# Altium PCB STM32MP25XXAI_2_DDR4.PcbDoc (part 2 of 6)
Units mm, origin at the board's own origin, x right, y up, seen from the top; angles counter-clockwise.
Board outline 172 x 137 mm, 4 copper layers (Top Layer, Signal Layer 1, Signal Layer 2, Bottom Layer), stack 1.614 mm thick; 241 components, 153 nets, 1312 pads, 924 vias.
Unrouted connection lines stored in the file: 13.
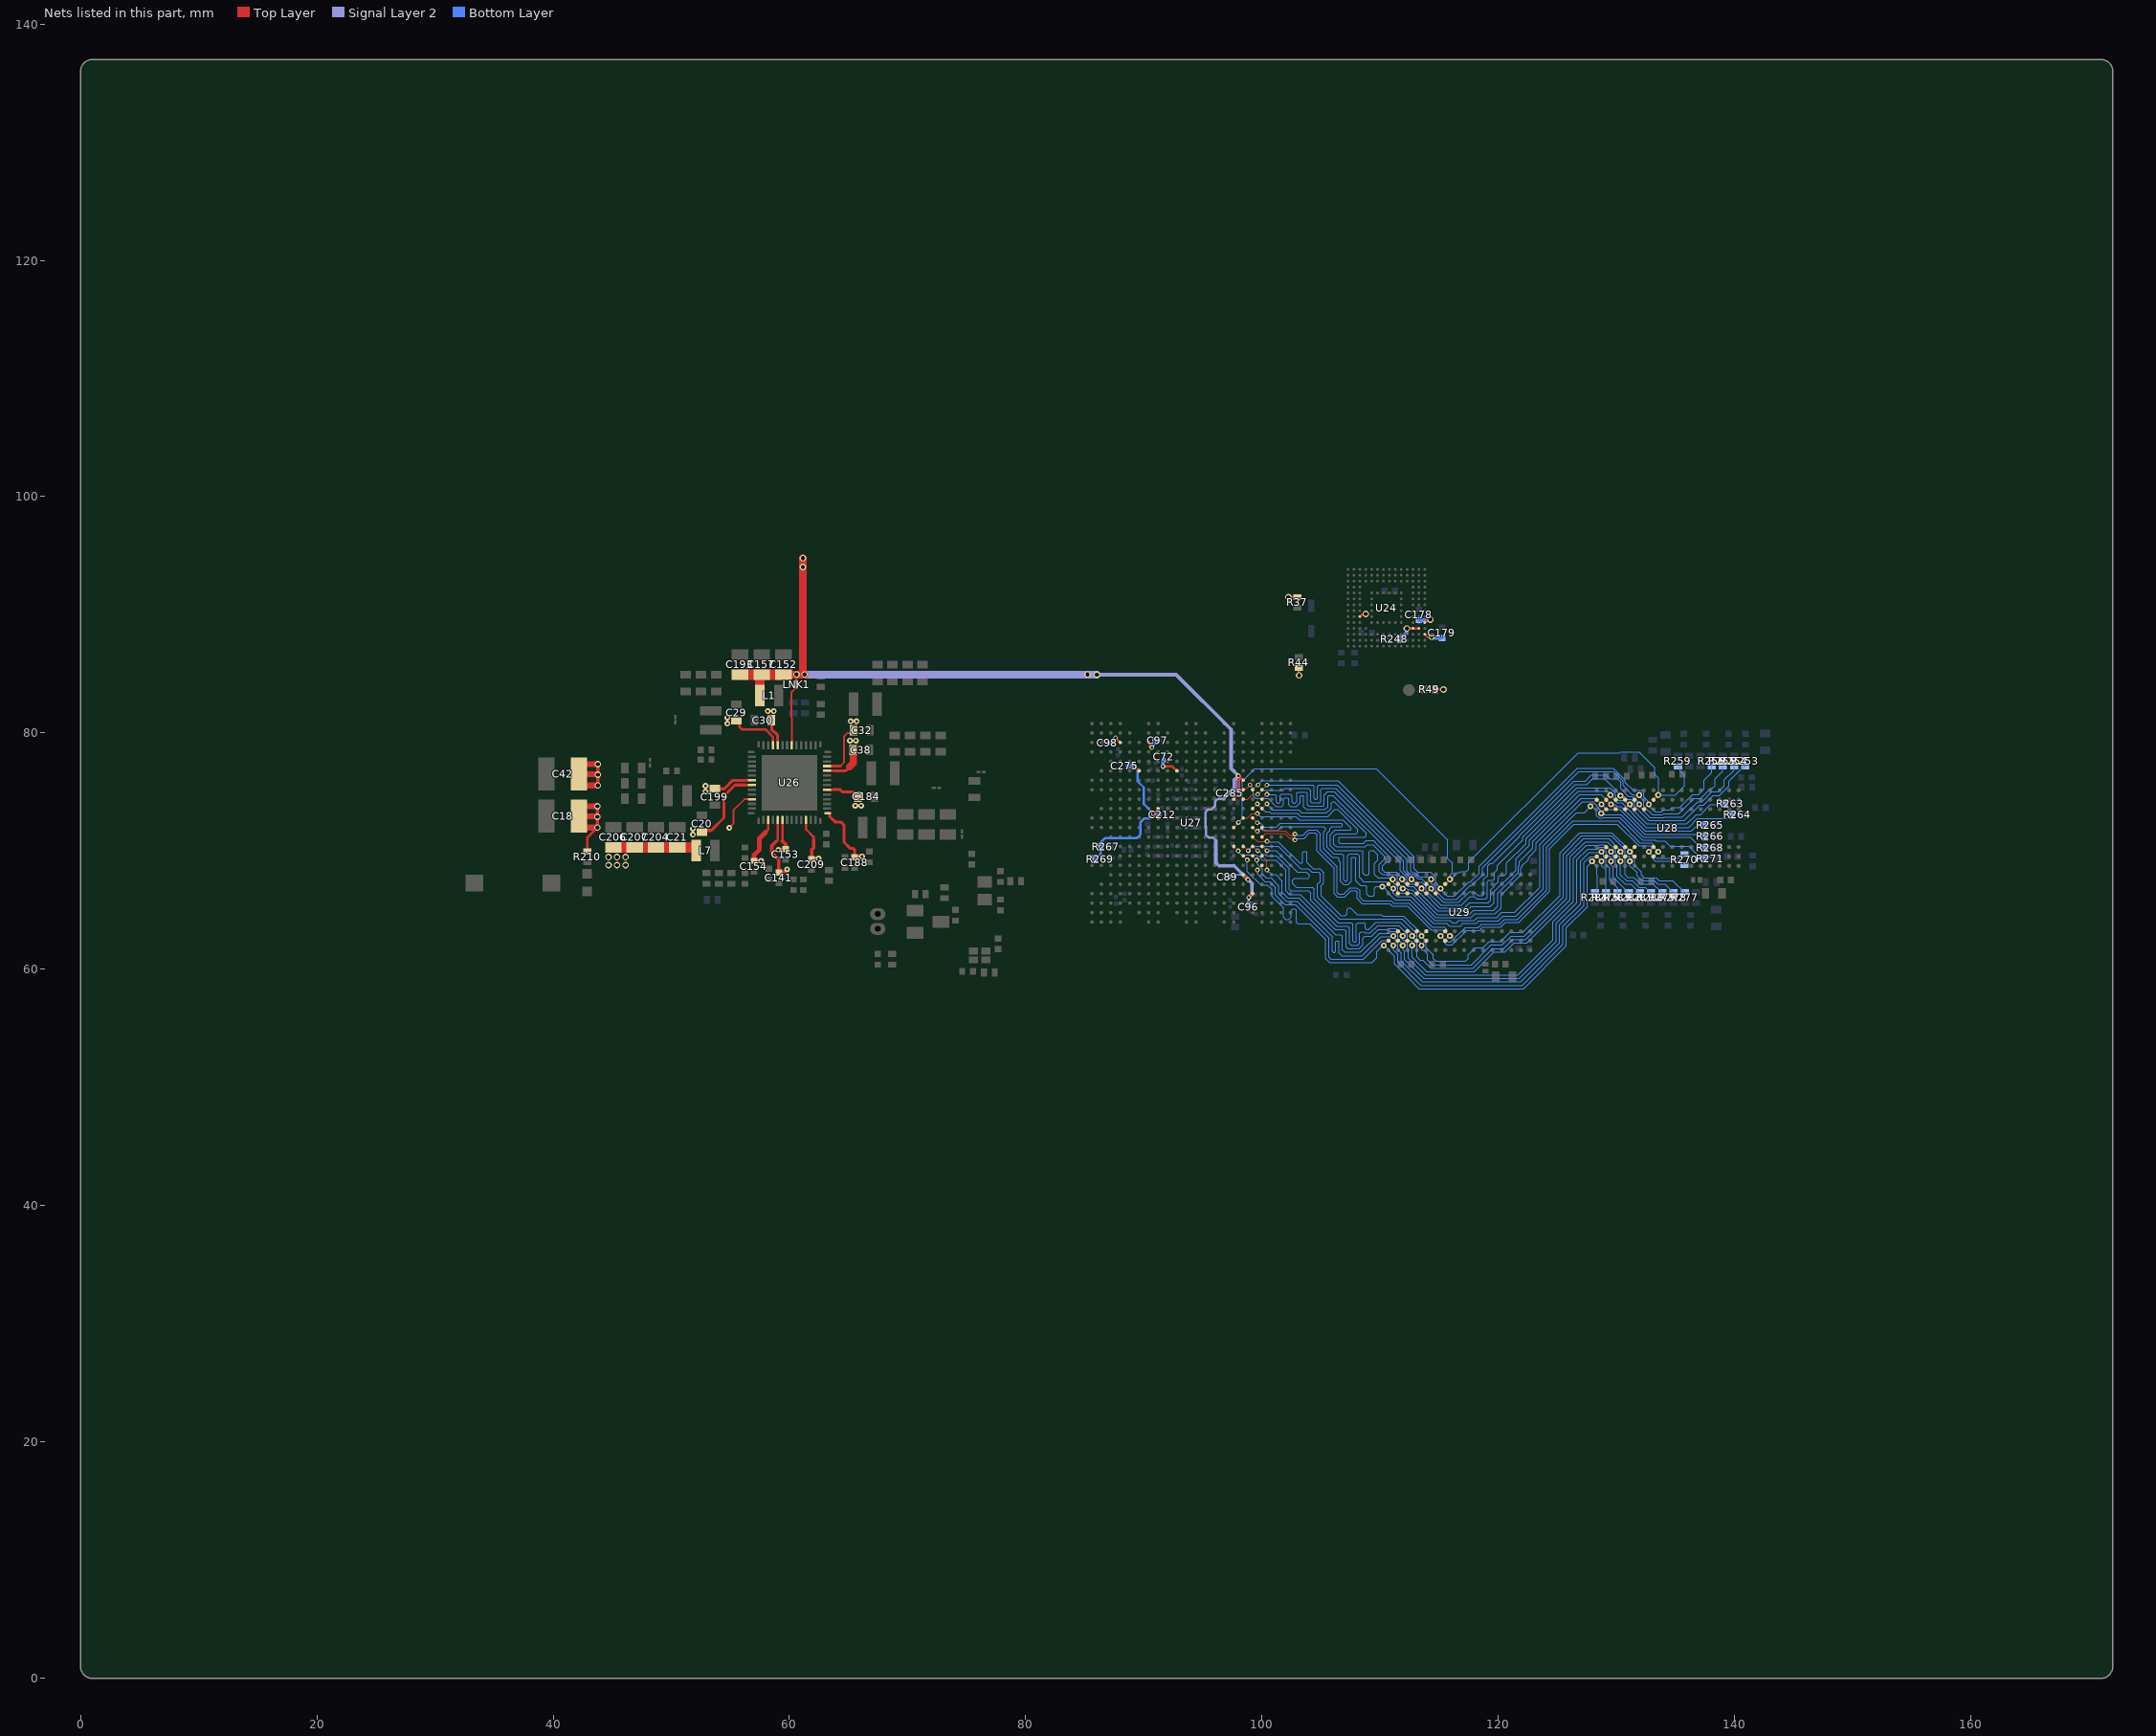
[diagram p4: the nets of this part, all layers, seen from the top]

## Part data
B2: library part MCD-03492, "Switch tactile, SPST-NO, 50mA, 12V, 6x3.8mm", Manufacturer="WURTH ELEKTRONIK", Manufacturer_Part_Number=434121025816, Package=6x3.8mm
C1 C2 C3 C4 C5 C6 C7 C8 C9 C10 C11 C12 C13 C14 C15 C16 C17 C25 C31 C44 C45 C46 C47 C52 C53 C54 C55 C56 C57 C58 C59 C60 C67: library part MCD-02377, "Capacitor, MLCC, 1uF, 6.3V, X5R, +/-20%, 0201, T=0,3mm", Alternate_Manufacturer=N/A, Manufacturer=MURATA, Manufacturer_Part_Number=GRM033R60J105MEA2, Package=0201
C18 C42: library part MCD-01796, "Capacitor, Tantalum, 100uF, 6V3, 40mR, +/-20%,  Type_B (3528 metric), T=1.9mm", Manufacturer=AVX, Manufacturer_Part_Number=TCJB107M006R0040, Package="3528 (metric)"
C19 C21 C152 C157 C186 C187 C193 C204 C206 C207: library part MCD-03139, "Capacitor, MLCC, 22uF, 10V, X5R, +/-20%, 0805, T=1,25mm", Manufacturer=MURATA, Manufacturer_Part_Number=GRM21BR61A226ME51L, Package=0805
C20 C29 C30 C32 C38 C184 C199: library part MCD-00099, "Capacitor, MLCC, 10uF, 10V, X5R, +/-10%, 0603, T=0,8mm", Alternate_Manufacturer=N/A, Manufacturer=MURATA, Manufacturer_Part_Number=GRM188R61A106KE69D, Package=0603
C22 C23 C24 C26 C27 C28 C34 C35 C36 C37 C41 C183 C200 C202: library part MCD-00100, "Capacitor, MLCC, 22uF, 6V3, X5R, +/-20%, 0603, T=0,8mm", Alternate_Manufacturer=N/A, Manufacturer=MURATA, Manufacturer_Part_Number=GRM188R60J226MEA0J, Package=0603
C33: library part MCD-00011, "Capacitor, MLCC, 10nF, 16V, X7R, 10%, 0402, T=0.5mm", Manufacturer=YAGEO, Manufacturer_Part_Number=CC0402KRX7R7BB103, Package=0402
C39 C40: library part MCD-03140, "Capacitor, MLCC, 10uF, 6.3V, X5R, +/-20%, 0402, T=0.5mm", Manufacturer=MURATA, Manufacturer_Part_Number=GRM155R60J106ME05D, Package=0402
C43 C153 C154 C188: library part MCD-00095, "Capacitor, MLCC, 1uF, 25V, X5R, +/-10%, 0402, T=0.5mm", Manufacturer=MURATA, Manufacturer_Part_Number=GRM155R61E105KA12, Package=0402
C48 C49 C50 C51 C76 C77 C78 C80 C82 C83 C84 C93 C94 C95 C177 C179 C182 C211 C226 C238 C239 C245 C247 C255 C256 C257 C258 C259 C261 C262 C264 C276 C277 C279 C280 C282 C283 C284: library part MCD-00006, "Capacitor, MLCC, 100nF, 16V, X7R, +/-10%, 0402, T=0.5mm", Alternate_Manufacturer=MURATA, Alternate_Manufacturer_Part_Number=GCM155R71C104KA55D, Manufacturer=YAGEO, Manufacturer_Part_Number=CC0402KRX7R7BB104, Package=0402
C61: library part MCD-01534, "Capacitor, MLCC, 4,7uF, 6V3, X5R, +/-20%, 0201, T=0.5mm", Alternate_Manufacturer=N/A, Manufacturer=MURATA, Manufacturer_Part_Number=GRM035R60J475ME15, Package=0201
C62 C63 C64 C65 C66 C68 C69 C70 C71 C72 C73 C74 C75 C89 C96 C97 C98 C212 C234 C275 C285: library part MCD-01535, "Capacitor, MLCC,100nF, 10V, X7R, +/-10%, 0201, T=0.3mm", Alternate_Manufacturer=N/A, Manufacturer=MURATA, Manufacturer_Part_Number=GRM033R61A104KE15, Package=0201
C79: library part MCD-02235, "Capacitor, MLCC, 2.2uF, 10V, X5R,+/-10%, 0201, T=0.5mm", Manufacturer=MURATA, Manufacturer_Part_Number=GRM033R61A225KE47D, Package=0201
C81 C86 C90 C92: library part MCD-00674, "Capacitor, MLCC, 6.8pF, 50V, NPO, +-0.25pF, 0402, T=0.5mm", Alternate_Manufacturer=N/A, Manufacturer=YAGEO, Manufacturer_Part_Number=CC0402CRNPO9BN6R8, Package=0402
C85 C99 C236 C278: library part MCD-01341, "Capacitor, MLCC, 10uF, 6V3, X5R, +/-20%, 0603, T=0,8mm", Alternate_Manufacturer=MURATA, Alternate_Manufacturer_Part_Number=GRM188R60J106ME84D, Manufacturer_Part_Number=GRM188R60J106ME47D, Package=0603
C87: library part MCD-00006, "Capacitor,100nF,16V,X7R,10%,0402", Alternate_Manufacturer=MURATA, Alternate_Manufacturer_Part_Number=GCM155R71C104KA55D, Manufacturer=YAGEO, Manufacturer_Part_Number=CC0402KRX7R7BB104, Package=0402
C88: library part MCD-01823, "Capacitor, MLCC, 2.2uF, 6V3, X5R,+/-10%, 0402, T=0.5mm", Alternate_Manufacturer=N/A, Manufacturer=MURATA, Manufacturer_Part_Number=GRM155R60J225KE95D, Package=0402
C91 C141 C142 C156 C189 C190 C208 C209 C217: library part MCD-01356, "Capacitor, MLCC, 4.7uF, 6V3, X5R, +/-20%, 0402, T=0.5mm", Manufacturer=MURATA, Manufacturer_Part_Number=GRM155R60J475ME47, Package=0402
C155: library part MCD-02198, "Capacitor, MLCC, 10nF, 50V, X7R, +/-10%, 0402, T=0.5mm", Manufacturer=YAGEO, Manufacturer_Part_Number=CC0402KRX7R9BB103, Package=0402
C178 C180 C181: library part MCD-02606, "Capacitor, MLCC, 2.2uF, 6.3V, X5R, +/-10%, 0402, T=0.5mm", Manufacturer=YAGEO, Manufacturer_Part_Number=CC0402KRX5R5BB225, Package=0402
C254 C281: library part MCD-00099, "Capacitor, MLCC, 10uF, 10V, X5R, +/-10%, 0603, T=0.8mm", Manufacturer=MURATA, Manufacturer_Part_Number=GRM188R61A106KE69D, Package=0603
CN12: library part MCD-00655, "Header 2 circuits, 1.25mm Pitch ,  Vertical, with Friction Lock", Alternate_Manufacturer=N/A, Manufacturer=MOLEX, Manufacturer_Part_Number=53047-0210
D5: library part MCD-00034, Manufacturer=STMICROELECTRONICS, Manufacturer_HQ_COO=EU, Package=SOD323
D6: library part MCD-03280, "Diode, Schottky, Dual Common Cathode, 0V3, 300mA, 40V, SOT-23", Manufacturer=STMICROELECTRONICS, Manufacturer_Part_Number=BAT54CFILM, Package=SOT23
L1 L6: library part MCD-03143, "Inductor, 2.2uH, +/-20%, Itemp= 1700mA, Isat= 2400mA, 0R140, 0806, T=1mm", Manufacturer=MURATA, Manufacturer_Part_Number=DFE201610E-2R2M{}P2, Package=0806
L2 L4: library part MCD-03142, "Inductor, 0.68uH, +/-20%, Itemp= 3900mA, Isat= 5400mA, 0R031, 1008, T=1.2mm", Manufacturer=MURATA, Manufacturer_Part_Number=DFE252012F-R68M{}P2, Package=1008
L3 L5 L7: library part MCD-03141, "Inductor, 0.68uH, +/-20%, Itemp= 3100mA, Isat= 4300mA, 0R043, 0806, T=1mm", Manufacturer=MURATA, Manufacturer_Part_Number=DFE201610E-R68M{}P2, Package=0806
LD11: library part MCD-00588, "LED Green, 0603 SMD, Forward Voltage Typ=2V, Max=2.5V", Alternate_Manufacturer="VISHAY SEMICONDUCTOR OPTO DIVISION", Alternate_Manufacturer_Part_Number=VLMTG1300-GS08, Manufacturer="OSRAM OPTO SEMICONDUCTORS", Manufacturer_Part_Number="LG Q396-PS-35", Package=0603
LNK1 LNK2 LNK4 LNK7 LNK8 LNK11: library part MCD-02777, "Track link on PCB 200um width for layout routing", Manufacturer=N/A
R2 R46 R57 R59 R60 R64 R75 R81 R267 R269 R286: library part MCD-00052, "Resistor,0R,0402,5%,1/16W", Alternate_Manufacturer=N/A, Manufacturer=YAGEO, Manufacturer_Part_Number=RC0402JR-070RL, Package=0402
R27 R252 R272: library part MCD-00053, "Resistor,10K,0402,1%,1/16W", Alternate_Manufacturer=N/A, Manufacturer=YAGEO, Manufacturer_Part_Number=RC0402FR-0710KL, Package=0402
R37 R44 R49 R248: library part MCD-00053, "Resistor,10K,0402,1%,1/16W", Manufacturer=YAGEO, Manufacturer_Part_Number=RC0402FR-0710KL, Package=0402
R63 R73 R262: library part MCD-02253, "Resistor,240R,0201,1%,1/20W", Alternate_Manufacturer=N/A, Manufacturer=YAGEO, Manufacturer_Part_Number=RC0201FR-07240RL, Package=0201
R66: library part MCD-00058, "Resistor, 20R, 0402, +/-1%, 1/16W", Alternate_Manufacturer=N/A, Manufacturer=YAGEO, Manufacturer_Part_Number=RC0402FR-0720RL, Package=0402
R67: library part MCD-00052, "Resistor, 0R, 0402, +/-5%, 1/16W", Manufacturer=YAGEO, Manufacturer_Part_Number=RC0402JR-070RL, Package=0402
R210: library part MCD-00441, "Resistor,270R,0402,1%,1/16W", Manufacturer=YAGEO, Manufacturer_Part_Number=RC0402FR-07270RL, Package=0402
R249: library part MCD-00056, "Resistor, 0R, 0603, +/-5%, 1/10W", Manufacturer=YAGEO, Manufacturer_Part_Number=RC0603JR-070RL, Package=0603
R253 R254 R255 R256 R257 R258 R259 R263 R264 R265 R266 R268 R271 R273 R275 R276 R277 R278 R279 R280 R281 R282 R283 R284: library part MCD-00054, "Resistor, 56R, 0402, +/-1%, 1/16W", Alternate_Manufacturer=N/A, Manufacturer=YAGEO, Manufacturer_Part_Number=RC0402FR-0756RL, Package=0402
R260 R261: library part MCD-00068, "Resistor,1K5,0402,1%,1/16W", Manufacturer=YAGEO, Manufacturer_Part_Number=RC0402FR-071K5L, Package=0402
R270: library part MCD-01819, "Resistor,100R,0402,0,5%,1/16W,±100ppm/°C", Alternate_Manufacturer=N/A, Manufacturer=YAGEO, Manufacturer_Part_Number=RC0402DR-07100RL, Package=0402
R300 R301 R302 R303: library part MCD-00061, "Resistor, 1K, 0402, +/-1%,1/16W", Manufacturer=YAGEO, Manufacturer_Part_Number=RC0402FR-071KL, Package=0402
TP9: library part MCD-00074, "Test Point 1mm", Manufacturer=n/a, Manufacturer_HQ_COO=Unknown
U24: library part MCD-02799, "Memory, eMMC, 4GB, 15nm ,WFBGA , 153 pins", Manufacturer=KIOXIA, Manufacturer_Part_Number=THGBMTG5D1LBAIL, Package=WFBGA153
U26: library part MCD-03000, "STPMIC2", Manufacturer=STMICROELECTRONICS, Package=VQFN
U27: library part MCD-02000, "MPU, ARM Cortex-A35 + M33 32-bit MPU, 808KB RAM, With Crypto", Manufacturer=STMICROELECTRONICS, Manufacturer_HQ_COO=EU, Package=LFBGA-436
U28: library part MCD-03523, "Memory, DDR4 SDRAM, 1V2, 16Gbit, FBGA96", Manufacturer=MICRON, Package=FBGA-96
U29: library part MCD-03523, "Memory, DDR4 SDRAM, 1V2, 16Gbit, 1.6 GHz, FBGA96", Manufacturer=MICRON, Package=FBGA-96
X1: library part MCD-01479, "Crystal, 32.768kHz, 6pF, +/-20ppm, 80K, 2.05x1.2mm", Manufacturer=NDK, Manufacturer_Part_Number=NX2012SA-32.768KHZ-EXS00A-MU00527, Package=2.05x1.2mm
X2: library part MCD-02344, "Crystal, 40MHz, 6pF, +/-20ppm, 80R, 1.6x1.2mm", Manufacturer=NDK, Manufacturer_Part_Number=NX1612SA-40MHZ-EXS00A-CS13836, Package=1.6x1.2mm

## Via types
v1: diameter 0.55, hole 0.35, Top Layer to Bottom Layer, 432 vias
v2: diameter 0.4, hole 0.2, Top Layer to Bottom Layer, tented both sides, 202 vias
v3: diameter 0.5, hole 0.2, Top Layer to Bottom Layer, 146 vias
v4: diameter 0.5, hole 0.25, Top Layer to Bottom Layer, 144 vias

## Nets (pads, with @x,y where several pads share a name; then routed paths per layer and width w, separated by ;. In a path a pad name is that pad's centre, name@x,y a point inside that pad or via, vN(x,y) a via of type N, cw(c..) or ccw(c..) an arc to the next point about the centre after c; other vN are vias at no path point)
1V8: C72.2 C89.2 C96.2 C97.2 C98.2 C152.2 C157.2 C178.2 C179.2 C193.2 C212.2 C275.2 C285.2 L1.2 LNK1.2 R37.2 R44.2 R49.2 R248.2 R267.2 R269.1 U24.C6 U24.M4 U24.N4 U24.P3 U24.P5 U27.C4 U27.C7 U27.F6 U27.F10 U27.G17 U27.J16 U27.K8 U27.L8 U27.U17 U27.W18 | length 110.6
  Top Layer w0.2: LNK1.2@60.6,84.348 v1(60.6,84.95) ; v2(87.6,79.6) U27.C4@88,79.2 v2(87.6,79.6) ; v2(89.2,77.2) U27.F6@89.6,76.8 ; U27.C7@90.4,79.2 90.415,79.185 90.415,79.02 v2(90.66,78.775) ; U27.L8@91.2,72.8 91.175,72.8 v2(90.8,73.175) 91.2,73.575 U27.K8@91.2,73.6 ; v2(91.624,77.173) 92.413,77.173 92.786,76.8 U27.F10@92.8,76.8 ; U27.J16@97.6,74.4 98,74.8 v2(98,76.375) 98.012,76.375 98.388,76 U27.G17@98.4,76 ; U27.U17@98.4,68 v2(98.8,67.6) ; v2(98.868,66.067) U27.W18@99.2,66.4 ; v1(102.23,91.5) R37.2@102.975,91.5 ; R44.2@103.1,85.528 103.125,85.503 v1(103.125,84.875) ; U24.C6@108.275,89.85 108.452,90.027 108.727,90.027 v1(108.775,90.075) ; v1(112.25,88.85) U24.M4@112.775,88.85 U24.N4@113.275,88.85 ; U24.P3@113.775,88.35 113.975,88.15 v1(114.35,88.15) ; U24.P5@113.775,89.35 114.005,89.58 114.23,89.58 v1(114.25,89.6) ; R49.2@114.625,83.685 v1(115.35,83.685)
  Top Layer w0.64: C152.2@59.5,84.95 v1(60.6,84.95) v1(61.28,84.95) 61.142,85.088 v1(61.142,94.8)
  Top Layer w0.8: L1.2@57.495,83.175 57.495,84.9 57.545,84.95 C157.2@57.65,84.95
  Top Layer w0.9: C193.2@55.8,84.95 C157.2@57.545,84.95 ; C157.2@57.65,84.95 C152.2@59.5,84.95
  Signal Layer 2 w0.2: 96.075,70.9 95.825,71.15 95.484,71.15 95.399,71.235 95.248,71.386 95.248,72.063 95.201,72.109 95.201,73.292 95.317,73.408 95.317,73.433 95.434,73.55 95.723,73.55 96.007,73.834 96.007,74.166 96.003,74.169 96.257,74.423 96.684,74.423 ; v2(98.868,66.067) v2@98.868,66.094
  Signal Layer 2 w0.3: v1(86.019,84.939) 92.721,84.939 97.371,80.289 97.371,77.004 v2(98,76.375) ; 96.075,70.9 96.075,69.048 96.075,69.014 96.339,68.75 97.65,68.75 v2(98.8,67.6) ; 96.684,74.423 97.65,75.389 97.65,76.018 v2@98,76.367 ; v2(98.8,67.6) 99.15,67.25 99.15,66.377 v2@98.868,66.094
  Signal Layer 2 w0.64: v1@60.6,84.955 v1@61.28,84.955 ; v1(61.28,84.95) 86.009,84.95 v1(86.019,84.939)
  Bottom Layer w0.17: C89.2@97.35,67.825 97.415,67.89 97.44,67.89 97.56,68.01 98.39,68.01 v2(98.8,67.6)
  Bottom Layer w0.2: R269.1@85.854,69.315 85.854,69.41 86.009,69.565 86.104,69.565 86.35,69.811 R267.2@86.35,70.375 ; R267.2@86.325,70.715 86.697,71.087 89.377,71.087 89.723,71.434 89.723,72.448 90.059,72.783 90.457,72.783 90.8,73.127 v2(90.8,73.175) ; v2(89.2,77.2) 89.458,76.942 89.458,75.927 89.985,75.4 89.985,73.99 v2(90.8,73.175) ; v2(90.66,78.775) 90.66,78.79 90.825,78.955 C97.2@90.825,79.375 ; C212.2@91.31,73.1 91.272,73.138 90.837,73.138 v2(90.8,73.175) ; C96.2@98.85,65.55 98.85,66.05 v2(98.868,66.067)
  Bottom Layer w0.3: C98.2@87.175,79.175 v2(87.6,79.6) ; C72.2@91.6,77.7 91.6,77.224 91.624,77.2 v2(91.624,77.173) ; C285.2@97.555,74.91 97.94,75.295 97.94,76.288 98,76.348 v2(98,76.375) ; R248.2@111.675,87.95 112.241,88.516 112.241,88.841 v1(112.25,88.85) ; C178.2@113.275,89.55 114.132,89.55 114.182,89.6 v1(114.25,89.6) ; v1(114.35,88.15) 114.418,88.15 114.543,88.025 C179.2@115.225,88.025
  Bottom Layer w0.4: C275.2@88.675,77.2 v2(89.2,77.2)
  other v1: 85.224,84.95 61.131,94.047
1V8_FB: LNK1.1 U26.35 | length 5.1
  Top Layer w0.15: U26.35@60.2,78.97 60.2,81.311 60.175,81.336 60.175,83.473 LNK1.1@60.6,83.898
3V3: C21.2 C154.2 C204.2 C206.2 C207.2 L7.2 U26.3 U26.53 | length 15.3
  Top Layer w0.15: v3(54.91,71.977) 55.262,72.329 55.262,73.465 56.197,74.4 U26.53@56.83,74.4 ; U26.53@56.62,74.369 56.919,74.369 U26.53@56.95,74.4
  Top Layer w0.21: 57.973,71.598 58.2,71.825 U26.3@58.2,72.63
  Top Layer w0.3: C154.2@56.975,69.175 C154.2@57,69.175 v3@57.585,69.175
  Top Layer w0.4: C154.2@57,69.175 57.014,69.189 57.014,69.685 57.46,70.131 57.46,71.085 57.973,71.598
  Top Layer w0.9: C206.2@45.087,70.323 C21.2@50.5,70.323 51.862,70.323 L7.2@51.887,70.298
  other v1: 44.687,68.823 45.412,68.823 46.137,68.823 44.687,69.498 45.412,69.498 46.137,69.498
  other v3: 57.61,69.175
5V_STLK: C18.1 C20.2 C29.2 C30.2 C32.2 C38.2 C42.1 C153.2 C184.2 C188.2 C199.2 C209.2 R210.1 U26.6 U26.11 U26.15 U26.20 U26.24 U26.25 U26.38 U26.39 U26.49 U26.50 | length 56.5
  Top Layer w0.15: 64.3,77.2 64.625,77.525 64.625,79.731 64.888,79.994 65.319,79.994 C32.2@65.425,80.1
  Top Layer w0.2: R210.1@42.887,69.97 42.887,71.138 v1(43.751,72.002)
  Top Layer w0.21: C29.2@55.525,81.05 55.762,80.813 55.762,80.513 55.975,80.3 57.964,80.3 58.6,79.664 U26.39@58.6,78.97 ; 56.275,75.6 U26.50@56.83,75.6 ; 56.275,76 U26.49@56.83,76 ; U26.38@59,78.97 59,79.525 ; 59.4,70.85 U26.6@59.4,72.63 ; U26.11@61.4,72.63 61.4,71.843 62.04,71.203 62.04,70.975 ; U26.15@63.17,73.2 U26.15@63.245,73.2 U26.15@63.285,73.2 ; U26.20@63.17,75.2 63.725,75.2 ; U26.24@63.17,76.8 63.725,76.8 ; U26.25@63.17,77.2 64.3,77.2
  Top Layer w0.25: C20.2@52.6,71.75 53.375,71.75 54.45,72.825 54.45,74.669 55.381,75.6 56.275,75.6 ; C199.2@53.675,75.275 54.491,75.275 55.216,76 56.275,76 ; C30.2@58.425,81.075 58.494,81.006 58.494,80.308 59,79.802 59,79.525 ; 63.395,73.095 63.395,72.947 63.871,72.472 64.353,72.472 64.625,72.2 64.625,70.759 65.134,70.25 65.379,70.25 65.525,70.104 C188.2@65.525,69.55 ; 63.725,75.2 64.288,75.2 64.463,75.025 65.347,75.025 65.472,74.9 65.55,74.9 65.747,74.703 C184.2@65.747,74.625 ; 63.725,76.8 64.75,76.8 65.075,77.125
  Top Layer w0.3: v1(43.751,72.002) v1(43.751,72.902) v1(43.751,73.802) ; v1(43.776,75.565) v1(43.776,76.465) v1(43.776,77.365) ; v3(59.065,70.11) 59.675,70.11 59.674,70.111 59.674,70.576 59.4,70.85 ; C209.2@61.85,69.38 C209.2@61.875,69.38 ; 62.04,70.975 62.04,70.269 61.875,70.104 C209.2@61.875,69.38 ; v3(62.46,69.38) C209.2@61.875,69.38 ; C188.2@65.525,69.55 v3(66.135,69.55)
  Top Layer w0.5: C18.1@42.187,72.049 42.235,72.002 v1(43.751,72.002) ; C18.1@42.187,72.961 43.679,72.961 43.737,72.902 v1(43.751,72.902) ; C42.1@42.187,75.612 42.235,75.565 v1(43.776,75.565) ; C42.1@42.187,76.523 43.704,76.523 43.762,76.465 v1(43.776,76.465) ; C18.1@42.246,73.802 v1(43.751,73.802) ; C42.1@42.246,77.365 v1(43.776,77.365)
  Top Layer w0.6: 65.075,77.125 65.4,77.45 C38.2@65.4,78.175
  other v3: 51.825,71.4 51.825,71.9 65.575,73.85 66.075,73.85 52.9,75.025 52.9,75.525 65.125,79.35 65.625,79.35 54.75,80.8 65.175,81 65.675,81 54.75,81.3 58.175,81.85 58.675,81.85
5V_VCONN: C141.1 U26.5 | length 5.7
  Top Layer w0.21: 58.877,70.828 59,70.95 U26.5@59,72.63
  Top Layer w0.3: 58.877,70.828 58.51,70.46 58.51,69.865 59.1,69.275 C141.1@59.1,68.2 59.539,68.2 v3(59.8,68.46)
DDR_A0: R265.1 U27.K18 U28.P3 U29.P3 | length 57.5
  Top Layer w0.09: U27.K18@99.2,73.6 v2(99.6,74) ; v4(111.9,66.825) 111.941,66.825 112.294,66.472 U29.P3@112.294,66.422 ; v4@129.532,73.928 129.572,73.928 129.925,73.575 U28.P3@129.925,73.55 U28.P3@129.925,73.525
  Bottom Layer w0.09: v2(99.6,74) 100.267,73.333 100.646,73.333 100.771,73.209 102.988,73.209 103.252,72.945 105.581,72.945 106.158,73.522 106.2,73.522 106.384,73.522 108.091,71.815 108.091,71.615 107.965,71.49 106.3,71.49 106.077,71.267 106.077,70.58 106.3,70.357 108.748,70.357 ; 108.748,70.359 108.914,70.526 109.38,70.526 110.359,69.547 110.359,69.324 109.909,68.874 109.909,68.291 110.177,68.022 111.269,68.022 111.449,67.842 111.449,67.352 111.894,66.908 v4@111.938,66.863 ; v4(111.9,66.825) 111.938,66.862 112.233,66.862 112.365,66.73 112.708,66.73 114.805,64.633 117.533,64.633 117.9,65 119.589,65 119.939,65.349 119.939,66.445 121.7,68.206 121.7,68.718 121.76,68.779 121.76,69.109 122.92,70.269 122.92,70.811 126.885,74.775 128.71,74.775 129.525,73.959 v4(129.525,73.95) ; v4@129.551,73.95 129.885,73.95 130.04,73.795 130.363,73.795 132.433,71.725 136.35,71.725 136.825,72.2 R265.1@137.5,72.2
DDR_A1: R281.1 U27.P16 U28.P7 U29.P7 | length 54.7
  Top Layer w0.09: U27.P16@97.6,70.4 v2(97.975,70.025) ; v4(111.9,62.825) U29.P7@112.3,63.225 ; v4@129.54,69.936 U28.P7@129.932,70.328
  Bottom Layer w0.09: v2(97.975,70.025) 97.975,69.95 98.25,69.675 99.45,69.675 99.53,69.595 99.693,69.595 100.029,69.259 101.146,69.259 101.995,68.41 101.995,66.636 102.285,66.347 103.212,66.347 106.181,63.378 106.972,63.378 107.099,63.25 107.099,61.878 107.235,61.742 108.219,61.742 108.555,62.078 108.555,62.657 108.702,62.804 109.281,62.804 109.834,63.357 110.575,63.357 110.675,63.457 111.319,63.457 111.37,63.405 111.9,62.875 v4(111.9,62.825) ; v4@111.9,62.816 111.9,62.504 111.985,62.42 112.064,62.42 112.295,62.189 112.295,61.694 112.365,61.624 112.365,60.958 113.803,59.52 121.655,59.52 124.605,62.47 124.605,64 126.361,65.756 126.361,69.387 127.456,70.482 128.43,70.482 128.483,70.535 129.004,70.535 129.525,70.014 v4(129.525,69.95) 129.525,69.9 129.725,69.7 129.725,69.509 129.92,69.314 129.92,68.88 130.035,68.765 130.035,67.886 130.722,67.2 131.225,67.2 131.9,66.525 R281.1@131.975,66.525
DDR_A2: R268.1 U27.L18 U28.R3 U29.R3 | length 60.6
  Top Layer w0.09: U27.L18@99.2,72.8 v2(99.6,72.4) ; v4(111.1,66.825) 111.141,66.825 111.494,66.472 U29.R3@111.494,66.422 ; v4(128.703,73.185) 128.781,73.263 128.781,73.381 128.908,73.508 129.084,73.508 U28.R3@129.125,73.55
  Bottom Layer w0.09: v2(99.6,72.4) 99.622,72.378 99.872,72.378 100.195,72.055 101.218,72.055 101.528,72.365 106.721,72.365 106.794,72.291 106.794,72.149 106.716,72.07 105.894,72.07 105.758,71.934 105.758,71.768 105.497,71.508 105.497,70.339 106.06,69.777 106.75,69.777 106.925,69.602 106.925,67.578 107.028,67.475 107.168,67.475 107.254,67.56 107.254,69.636 107.395,69.777 108.048,69.777 108.235,69.59 108.235,67.779 108.578,67.437 110.489,67.437 v4(111.1,66.825) 111.103,66.823 111.103,66.466 111.409,66.16 112.571,66.16 114.598,64.133 115.925,64.133 ; 115.925,64.132 116.116,63.94 116.457,63.94 116.65,64.133 117.958,64.133 118.21,64.385 ; 118.212,64.385 118.227,64.401 119.865,64.401 120.277,64.813 121.373,64.813 123.5,66.94 123.5,70.57 127.125,74.195 127.964,74.195 128.055,74.104 128.277,73.882 128.277,73.84 128.635,73.482 128.635,73.253 v4(128.703,73.185) 128.778,73.109 130.37,73.109 132.282,71.197 ; 132.28,71.195 136.23,71.195 137.125,70.3 R268.1@137.5,70.3
DDR_A3: R279.1 U27.P19 U28.N7 U29.N7 | length 57
  Top Layer w0.09: U27.P19@100,70.4 100.038,70.4 100.388,70.05 v2(100.425,70.05) ; v4(112.7,62.825) 112.724,62.825 113.094,63.195 U29.N7@113.094,63.222 ; v4@130.355,69.928 130.725,70.298 U28.N7@130.725,70.325
  Bottom Layer w0.09: v2(100.425,70.05) 101.175,70.05 102.992,68.234 103.762,68.234 103.993,68.003 103.993,67.765 103.94,67.713 102.738,67.713 102.575,67.55 102.575,67.25 102.898,66.927 104.298,66.927 104.415,66.81 104.415,65.963 106.421,63.958 107.549,63.958 107.679,63.828 107.679,62.403 107.759,62.322 107.922,62.322 107.975,62.375 107.975,63.81 108.123,63.958 108.606,63.958 108.725,63.839 108.725,63.481 108.822,63.384 109.037,63.384 109.631,63.978 111.711,63.978 112.661,63.028 112.661,62.864 v4(112.7,62.825) 112.7,62.775 112.9,62.575 112.9,62.384 113.104,62.18 113.104,61.046 113.37,60.78 113.595,60.78 114.275,60.1 117.854,60.1 119.521,61.767 120.455,61.767 121.221,62.533 122.318,62.533 125.781,65.997 125.781,69.627 127.204,71.05 129.338,71.05 130.17,70.217 130.17,70.208 130.325,70.053 130.325,69.9 130.513,69.713 130.513,69.588 130.6,69.5 130.6,69.434 130.72,69.314 130.72,68.021 130.939,67.803 131.443,67.803 132.021,67.225 133.086,67.225 133.376,66.935 133.389,66.935 133.39,66.934 133.417,66.934 133.825,66.525 R279.1@133.875,66.525
  other v4: 130.325,69.95
DDR_A4: R263.1 U27.H17 U28.N3 U29.N3 | length 59.9
  Top Layer w0.09: U27.H17@98.4,75.2 98.419,75.219 98.604,75.219 v2@98.98,75.595 ; U29.N3@113.094,66.422 113.094,66.47 113.449,66.825 v4@113.5,66.825 ; U28.N3@130.725,73.525 130.725,73.573 131.102,73.95 v4(131.125,73.95)
  Bottom Layer w0.09: v2(98.98,75.6) 99.255,75.325 99.255,74.682 99.484,74.453 100.517,74.453 101.181,73.789 101.696,73.789 101.829,73.922 101.829,74.427 101.924,74.522 102.164,74.522 102.256,74.429 102.256,73.922 102.389,73.789 102.904,73.789 103.221,74.105 103.221,74.641 103.3,74.72 103.458,74.72 103.528,74.65 103.528,73.747 103.751,73.525 105.341,73.525 105.563,73.747 105.563,74.638 105.65,74.725 106.001,74.725 111.695,69.031 111.695,68.342 112.251,67.787 112.251,67.397 112.438,67.21 112.85,67.21 113.002,67.059 113.267,67.059 113.5,66.825 113.5,66.718 113.498,66.715 115.031,65.182 117.108,65.182 117.55,65.625 119.139,65.625 119.359,65.844 119.359,66.748 120.012,67.402 120.012,67.833 120.125,67.945 120.508,67.945 120.695,68.133 120.695,68.98 122.34,70.625 122.34,71.051 126.645,75.355 129.429,75.355 129.87,74.914 129.87,74.756 129.925,74.701 129.925,74.541 130.161,74.305 130.651,74.305 131.006,73.95 v4(131.125,73.95) 131.125,73.825 131.395,73.555 131.395,73.47 132.56,72.305 135.952,72.305 136.748,73.101 137.126,73.101 137.95,73.925 R263.1@139.2,73.925
  other v4: 113.5,66.85
DDR_A5: R282.1 U27.R19 U28.P8 U29.P8 | length 50.8
  Top Layer w0.09: U27.R19@100,69.6 100.4,69.2 v2(100.4,68.4) ; v4(111.9,62.025) 111.9,62.055 U29.P8@112.269,62.424 ; v4@129.532,69.158 U28.P8@129.901,69.527
  Bottom Layer w0.09: v2(100.4,68.4) 100.785,68.015 101.15,68.015 101.705,67.46 101.705,66.516 102.165,66.057 103.092,66.057 106.228,62.92 106.686,62.92 106.809,62.797 106.809,61.639 106.996,61.452 108.339,61.452 109.954,63.067 110.784,63.067 110.937,63.22 111.264,63.22 111.495,62.989 111.495,62.545 111.9,62.14 v4(111.9,62.025) 111.939,61.986 111.939,61.64 112.075,61.504 112.075,60.838 113.683,59.23 121.775,59.23 124.895,62.35 124.895,63.88 126.651,65.636 126.651,69.267 127.574,70.189 128.406,70.189 128.562,70.345 128.889,70.345 129.12,70.114 129.12,69.8 129.13,69.79 129.13,69.786 129.362,69.555 129.431,69.555 129.5,69.485 129.5,69.175 v4(129.525,69.15) 129.525,68.85 129.7,68.675 129.7,67.775 130.95,66.525 R282.1@131.025,66.525
DDR_A6: R264.1 U27.K19 U28.P2 U29.P2 | length 60.3
  Top Layer w0.09: U27.K19@100,73.6 v2(100.4,74) ; v4@111.9,67.6 111.916,67.6 112.283,67.233 U29.P2@112.308,67.233 ; v4(129.475,74.75) 129.5,74.75 129.9,74.35 U28.P2@129.925,74.35
  Bottom Layer w0.09: v2(100.4,74) 100.4,73.99 100.891,73.499 103.108,73.499 103.372,73.235 105.461,73.235 105.853,73.627 105.853,74.078 105.975,74.2 106.116,74.2 108.8,71.516 108.8,71.292 108.708,71.2 106.6,71.2 106.5,71.1 106.5,70.747 106.6,70.647 108.578,70.647 108.814,70.883 109.433,70.883 109.803,70.513 110.894,69.422 110.894,69.208 110.773,69.087 110.532,69.087 110.199,68.754 110.199,68.412 110.225,68.385 110.361,68.25 111.315,68.25 111.9,67.664 111.9,67.489 112.022,67.368 112.022,67.357 112.359,67.02 112.772,67.02 114.86,64.932 117.283,64.932 117.675,65.325 119.326,65.325 119.649,65.648 119.649,66.565 121.495,68.411 121.495,69.37 122.63,70.505 122.63,70.931 126.765,75.065 129.21,75.065 v4@129.5,74.775 ; v4(129.475,74.75) 129.745,74.48 129.745,74.37 130.03,74.085 130.432,74.085 132.502,72.015 136.126,72.015 136.861,72.75 139.327,72.75 139.431,72.855 139.59,72.855 139.8,73.065 R264.1@139.8,73.075
  other v4: 111.85,67.625
DDR_A7: R275.1 U27.T19 U28.R8 U29.R8 | length 48.8
  Top Layer w0.09: v2(99.6,68.4) U27.T19@100,68.8 ; v4(111.1,62.025) U29.R8@111.5,62.425 ; v4@128.732,69.128 U28.R8@129.132,69.528
  Bottom Layer w0.09: v2(99.6,68.4) 99.607,68.393 99.607,68.059 100.231,67.435 100.628,67.435 101.125,66.938 101.125,66.276 101.924,65.477 102.823,65.477 105.649,62.65 105.649,61.035 105.812,60.872 108.587,60.872 ; 108.587,60.873 110.132,62.417 110.134,62.417 110.137,62.42 110.705,62.42 v4(111.1,62.025) ; v4@111.107,62.025 111.126,62.006 111.126,61.633 111.495,61.264 111.495,60.598 113.443,58.65 122.015,58.65 125.475,62.11 125.475,63.64 127.231,65.396 127.231,69.026 127.75,69.545 128.337,69.545 v4@128.725,69.157 ; v4@128.732,69.15 128.757,69.125 128.757,68.776 129.12,68.413 R275.1@129.12,66.53
  other v4: 128.725,69.15
DDR_A8: R266.1 U27.L17 U28.R2 U29.R2 | length 60.5
  Top Layer w0.09: U27.L17@98.4,72.8 98.783,72.8 99.158,73.175 v2(99.6,73.175) ; v4@111.094,67.622 U29.R2@111.494,67.222 ; v4(128.725,73.95) U28.R2@129.125,74.35
  Bottom Layer w0.09: v2(99.6,73.175) 99.856,72.919 102.868,72.919 103.132,72.655 106.841,72.655 107.525,71.971 107.525,71.833 107.473,71.78 106.18,71.78 105.787,71.388 105.787,70.46 106.18,70.067 108.458,70.067 108.525,70 108.525,68.156 108.694,67.988 108.975,67.988 109.075,68.088 109.075,69.967 109.175,70.067 109.429,70.067 109.805,69.691 109.805,69.23 109.519,68.944 109.519,68.027 109.814,67.732 v4@110.873,67.732 ; v4@111.14,67.576 111.14,67.293 111.213,67.22 111.264,67.22 111.5,66.984 111.5,66.525 111.595,66.43 112.655,66.43 114.702,64.383 117.693,64.383 118.001,64.691 119.716,64.691 120.229,65.203 120.229,66.303 121.905,67.98 121.905,68.589 122.038,68.721 122.038,68.788 122.55,69.3 122.55,69.465 123.21,70.125 123.21,70.69 126.797,74.277 127.005,74.485 128.201,74.485 128.725,73.961 v4(128.725,73.95) 129.12,73.555 130.263,73.555 132.372,71.446 136.654,71.446 136.85,71.25 R266.1@137.5,71.25
  other v4: 111.05,67.625
DDR_A9: R283.1 U27.R18 U28.R7 U29.R7 | length 52.1
  Top Layer w0.09: U27.R18@99.2,69.6 v2(99.55,69.25) ; v4(111.1,62.825) 111.494,63.218 U29.R7@111.494,63.222 ; v4@128.732,69.928 129.125,70.321 U28.R7@129.125,70.325
  Bottom Layer w0.09: v2(99.55,69.25) 99.595,69.205 99.595,68.9 100.026,68.47 100.026,68.05 100.346,67.73 100.66,67.73 100.665,67.725 100.749,67.725 101.415,67.058 101.415,66.396 102.044,65.767 102.943,65.767 105.939,62.77 105.939,61.528 106.021,61.446 106.135,61.446 106.229,61.54 106.229,62.327 106.282,62.379 106.451,62.379 106.519,62.311 106.519,61.381 106.738,61.162 108.459,61.162 110.074,62.777 111.052,62.777 v4(111.1,62.825) 111.1,62.726 111.303,62.523 111.303,62.415 111.5,62.218 111.5,61.669 111.785,61.384 111.785,60.718 113.563,58.94 121.895,58.94 125.185,62.23 125.185,63.76 126.941,65.516 126.941,69.146 127.694,69.899 128.674,69.899 v4(128.725,69.95) ; v4@128.725,69.925 128.725,69.867 128.9,69.692 128.9,69.534 129.12,69.314 129.12,68.83 129.41,68.54 129.41,67.562 130.075,66.897 R283.1@130.075,66.525
DDR_A10: R254.1 U27.J17 U28.M3 U29.M3 | length 60
  Top Layer w0.09: U27.J17@98.4,74.4 98.783,74.4 99.183,74.8 v2(99.625,74.8) ; U29.M3@113.894,66.422 113.894,66.47 114.249,66.825 v4(114.3,66.825) ; U28.M3@131.525,73.55 131.525,73.573 v4@131.88,73.928
  Bottom Layer w0.09: v2(99.625,74.8) 99.632,74.8 99.977,75.145 101.792,75.145 101.948,75.3 103.933,75.3 104.108,75.125 104.108,74.2 104.204,74.105 104.886,74.105 104.983,74.203 104.983,75.2 105.088,75.305 106.242,75.305 112.275,69.271 112.275,68.325 112.58,68.02 112.814,68.02 113.187,67.647 113.531,67.647 114.091,67.087 114.091,67.083 114.3,66.873 v4(114.3,66.825) v4@114.3,66.717 ; v4@114.298,66.715 115.331,65.682 116.653,65.682 117.549,66.578 117.95,66.578 118.285,66.242 118.651,66.242 118.755,66.347 118.755,67.616 119.1,67.961 119.1,68.745 119.325,68.97 119.509,68.97 121.76,71.221 121.76,71.291 126.404,75.935 127.368,75.935 127.868,76.435 129.115,76.435 129.438,76.112 130.095,76.112 130.36,75.847 130.36,75.268 131.015,74.613 131.337,74.613 131.925,74.025 v4(131.925,73.95) 131.925,73.836 132.22,73.541 132.22,73.466 132.851,72.835 133.987,72.835 134.037,72.885 135.554,72.885 136.864,74.195 137.255,74.195 138.075,75.015 138.599,75.015 139.12,75.536 139.12,76.034 139.95,76.864 R254.1@139.95,77.175
DDR_A11: R271.1 U27.M18 U28.T2 U29.T2 | length 59.8
  Top Layer w0.09: U27.M18@99.2,72 99.237,72 99.562,71.675 v2(99.6,71.675) ; v4(110.175,67) 110.423,67 110.647,67.224 U29.T2@110.694,67.224 ; v4@127.797,73.798 U28.T2@128.326,74.327
  Bottom Layer w0.09: v2(99.6,71.675) 99.6,71.677 99.79,71.867 99.973,71.867 100.089,71.751 101.324,71.751 101.648,72.075 105.226,72.075 105.375,71.925 105.375,71.796 105.207,71.628 105.207,70.219 105.94,69.487 106.405,69.487 106.52,69.372 106.52,69.168 106.635,69.053 106.635,67.458 106.908,67.185 107.288,67.185 107.579,67.475 107.579,69.402 107.664,69.487 107.858,69.487 107.945,69.4 107.945,67.505 108.35,67.1 108.75,67.1 108.855,66.995 108.855,66.376 109.015,66.215 109.412,66.215 109.519,66.322 109.519,66.856 109.662,67 v4(110.175,67) 110.216,67 110.625,66.59 110.625,66.507 111.242,65.89 112.488,65.89 114.495,63.883 115.625,63.883 115.858,63.65 116.782,63.65 117.015,63.883 118.118,63.883 118.33,64.095 ; 118.332,64.095 118.347,64.111 119.985,64.111 120.397,64.523 121.493,64.523 123.79,66.82 123.79,70.45 126.59,73.25 127.266,73.25 127.8,73.784 v4(127.8,73.8) 127.907,73.8 128.301,73.406 128.301,73.028 128.539,72.79 128.866,72.79 128.919,72.842 130.297,72.842 132.18,70.959 133.217,70.959 133.327,70.85 134.1,70.85 134.545,70.405 136.12,70.405 137.175,69.35 R271.1@137.5,69.35
DDR_A12: R277.1 U27.N18 U28.M7 U29.M7 | length 56.3
  Top Layer w0.09: U27.N18@99.2,71.2 99.575,70.825 v2(100.425,70.825) ; v4(113.5,62.825) 113.524,62.825 113.894,63.195 U29.M7@113.894,63.222 ; v4@131.132,69.928 131.155,69.928 131.525,70.298 U28.M7@131.525,70.325
  Bottom Layer w0.09: v2(100.425,70.825) 100.45,70.8 101.386,70.8 103.202,68.984 103.334,68.984 103.438,69.087 103.438,69.885 103.525,69.973 103.7,69.973 103.791,69.882 103.791,69.046 104.31,68.528 104.9,68.528 105.225,68.202 105.225,67.308 104.995,67.078 104.995,66.204 106.661,64.538 107.038,64.538 107.19,64.69 107.19,65.07 107.327,65.206 107.474,65.206 108.035,64.645 110.092,64.645 110.217,64.52 111.99,64.52 113.422,63.088 113.422,62.903 v4(113.5,62.825) 113.711,62.614 113.711,62.373 113.895,62.189 113.895,61.84 114.505,61.23 114.505,60.911 114.737,60.68 117.214,60.68 117.45,60.916 117.45,61.234 118.042,61.825 118.704,61.825 119.227,62.348 120.216,62.348 120.981,63.113 122.077,63.113 125.2,66.236 125.2,69.866 126.884,71.55 129.608,71.55 131.125,70.033 v4(131.125,69.95) 131.35,69.725 131.35,69.556 131.522,69.385 131.522,68.795 132.105,68.211 132.105,67.986 132.337,67.755 133.377,67.755 133.617,67.515 133.629,67.515 133.63,67.514 134.746,67.514 135.735,66.525 R277.1@135.775,66.525
DDR_A13: R284.1 U27.R17 U28.T8 U29.T8 | length 51.4
  Top Layer w0.09: U27.R17@98.4,69.6 v2(98.75,69.25) ; v4(110.3,62.025) 110.3,62.055 U29.T8@110.669,62.424 ; v4@127.932,69.158 128.004,69.23 128.255,69.481 U28.T8@128.301,69.527
  Bottom Layer w0.09: v2(98.75,69.25) 98.75,68.29 99.895,67.145 100.456,67.145 100.835,66.765 100.835,66.156 101.804,65.187 101.804,64.422 101.985,64.242 102.274,64.242 102.453,64.42 102.453,64.976 102.602,65.125 102.764,65.125 102.907,64.982 102.907,63.977 103.017,63.867 104.022,63.867 105.359,62.53 105.359,60.908 105.685,60.582 109.315,60.582 109.698,60.965 109.698,61.503 110.22,62.025 v4(110.3,62.025) 111.204,61.121 111.204,60.438 112.167,59.475 113.282,58.36 122.135,58.36 125.765,61.99 125.765,63.52 127.521,65.276 127.521,68.734 127.925,69.138 v4(127.925,69.15) ; v4@127.925,69.125 128.323,68.728 128.323,67.936 128.375,67.884 128.375,66.725 R284.1@128.175,66.525
DDR_ACTN: R256.1 U27.H18 U28.L3 U29.L3 | length 54.5
  Top Layer w0.09: U27.H18@99.2,75.2 99.6,75.6 v2(99.65,75.6) ; U29.L3@114.694,66.422 114.694,66.47 115.049,66.825 v4(115.1,66.825) ; U28.L3@132.325,73.525 132.325,73.573 v4@132.68,73.928
  Bottom Layer w0.09: v2@99.658,75.6 100.003,75.945 106.422,75.945 112.855,69.511 112.855,68.531 113.136,68.25 114.234,68.25 114.695,67.789 114.695,67.291 115.1,66.886 115.1,66.755 115.656,66.2 116.288,66.2 117.473,67.385 117.624,67.385 118.362,68.123 118.362,68.484 118.362,68.713 126.664,77.015 129.73,77.015 130.74,76.005 130.74,75.805 131.4,75.145 132.089,75.145 132.09,75.144 132.325,74.909 132.325,74.582 132.647,74.26 132.647,74.028 v4(132.725,73.95) 132.725,73.852 133.262,73.315 133.788,73.315 133.948,73.475 134.475,73.475 134.703,73.703 135.361,73.703 136.433,74.775 136.919,74.775 137.425,75.281 137.425,76.024 138.05,76.65 R256.1@138.05,77.175
DDR_BA0: R253.1 U27.J19 U28.N2 U29.N2 | length 61.5
  Top Layer w0.09: U27.J19@100,74.4 v2(100.4,74.8) ; v4@112.644,67.628 112.697,67.628 113.094,67.231 U29.N2@113.094,67.222 ; v4(130.325,74.7) 130.371,74.7 130.698,74.373 U28.N2@130.725,74.373
  Bottom Layer w0.09: v2(100.4,74.8) 100.409,74.791 101.065,74.791 101.199,74.657 101.199,74.173 101.294,74.079 101.445,74.079 101.539,74.173 101.539,74.696 101.666,74.824 102.412,74.824 102.546,74.689 102.546,74.174 102.642,74.079 102.784,74.079 102.931,74.225 102.931,74.91 103.031,75.01 103.725,75.01 103.818,74.917 103.818,73.94 103.943,73.815 105.166,73.815 105.273,73.922 105.273,74.758 105.53,75.015 106.121,75.015 111.985,69.151 111.985,68.346 112.65,67.682 v4(112.65,67.625) 112.67,67.625 112.895,67.4 113.509,67.4 113.901,67.008 113.901,66.666 115.135,65.432 116.862,65.432 117.603,66.172 117.948,66.172 118.168,65.952 118.931,65.952 119.069,66.09 119.069,67.39 119.203,67.524 119.548,67.524 119.686,67.662 119.686,68.202 119.905,68.421 119.905,68.81 122.05,70.955 122.05,71.171 126.524,75.645 127.488,75.645 127.988,76.145 128.939,76.145 129.129,75.955 129.129,75.952 130.325,74.756 v4(130.325,74.7) 130.387,74.638 130.633,74.638 130.904,74.367 131.267,74.367 131.52,74.114 131.52,73.78 132.705,72.595 135.744,72.595 137.054,73.905 137.376,73.905 138.196,74.725 138.719,74.725 139.512,75.518 139.512,75.933 140.15,76.572 140.15,76.59 140.235,76.675 140.299,76.675 140.799,77.175 R253.1@140.9,77.175
DDR_BA1: R280.1 U27.P18 U28.N8 U29.N8 | length 53.8
  Top Layer w0.09: U27.P18@99.2,70.4 99.237,70.4 99.588,70.05 v2(99.625,70.05) ; v4(112.7,62.025) 112.7,62.055 U29.N8@113.069,62.424 ; v4@130.332,69.158 U28.N8@130.701,69.527
  Bottom Layer w0.09: v2(99.625,70.05) 99.648,70.05 99.974,69.724 100.264,69.724 100.38,69.607 101.208,69.607 102.285,68.53 102.285,66.756 102.405,66.637 103.928,66.637 104.125,66.44 104.125,65.843 106.301,63.668 107.22,63.668 107.389,63.499 107.389,62.214 107.571,62.032 108.099,62.032 108.265,62.198 108.265,63.04 108.375,63.15 108.646,63.15 108.702,63.094 109.157,63.094 109.771,63.708 111.576,63.708 112.299,62.985 112.299,62.531 112.428,62.402 112.613,62.402 112.7,62.315 v4(112.7,62.025) 112.7,61.033 113.924,59.81 117.974,59.81 119.641,61.477 120.575,61.477 121.341,62.243 122.438,62.243 126.071,65.876 126.071,69.507 127.365,70.8 129.234,70.8 129.92,70.114 129.92,69.796 130.162,69.555 130.245,69.555 130.3,69.5 130.3,69.175 v4(130.325,69.15) 130.325,68.006 130.832,67.5 131.335,67.5 131.9,66.935 132.44,66.935 132.85,66.525 R280.1@132.925,66.525
DDR_BG0: R255.1 U27.H19 U28.M2 U29.M2 | length 56.7
  Top Layer w0.09: U27.H19@100,75.2 v2(100.4,75.6) ; U29.M2@113.894,67.222 113.894,67.27 114.249,67.625 v4(114.3,67.625) ; U28.M2@131.525,74.325 131.525,74.373 v4@131.88,74.728
  Bottom Layer w0.09: v2(100.4,75.6) 104.298,75.6 104.398,75.5 104.398,74.479 104.482,74.395 104.612,74.395 104.693,74.476 104.693,75.468 104.825,75.6 106.357,75.6 112.565,69.391 112.565,68.304 112.659,68.21 112.892,68.21 113.263,67.84 114.045,67.84 114.26,67.625 v4(114.3,67.625) 114.3,67.306 114.387,67.22 114.464,67.22 114.7,66.984 114.7,66.666 115.435,65.932 116.463,65.932 117.626,67.095 117.744,67.095 118.652,68.003 118.652,68.152 118.652,68.593 126.784,76.725 129.751,76.725 130.55,75.926 130.55,75.558 131.304,74.803 131.416,74.803 131.469,74.75 v4(131.925,74.75) 131.925,74.647 132.32,74.252 132.32,73.786 132.317,73.783 133.025,73.075 133.888,73.075 133.988,73.175 135.244,73.175 136.554,74.485 137.135,74.485 137.955,75.305 138.089,75.305 138.32,75.536 138.32,76.107 139,76.787 R255.1@139,77.175
DDR_CASN: R278.1 U27.P17 U28.M8 U29.M8 | length 53.7
  Top Layer w0.09: U27.P17@98.4,70.4 98.45,70.4 98.8,70.05 v2@98.85,70.05 ; v4(113.5,62.025) 113.5,62.055 U29.M8@113.869,62.424 ; v4@131.132,69.158 U28.M8@131.501,69.527
  Bottom Layer w0.09: v2@98.85,70.05 99.2,70.4 101.376,70.4 103.252,68.524 103.904,68.524 104.19,68.238 104.78,68.238 104.935,68.082 104.935,67.439 104.705,67.209 104.705,66.084 106.541,64.248 111.852,64.248 113.095,63.004 113.095,62.557 v4@113.441,62.211 ; v4@113.449,62.203 v4@113.441,62.211 ; R278.1@134.825,66.525 134.788,66.525 134.089,67.224 133.51,67.224 133.509,67.225 133.497,67.225 133.207,67.515 132.141,67.515 131.753,67.903 131.725,67.93 131.725,68.175 131.125,68.775 v4(131.125,69.15) 131.132,69.156 131.132,69.506 131.083,69.555 130.962,69.555 130.73,69.786 130.73,69.795 130.72,69.805 130.72,70.134 129.554,71.3 127.044,71.3 125.49,69.746 125.49,66.116 122.198,62.823 121.101,62.823 120.335,62.057 119.401,62.057 117.734,60.39 114.395,60.39 113.997,60.789 113.997,61.287 113.664,61.62 113.555,61.62 113.5,61.675 v4(113.5,62.025) 113.441,62.084 v4@113.441,62.211
  other v2: 98.825,70.05
DDR_CKE: R259.1 U27.M16 U28.K2 U29.K2 | length 58.7
  Top Layer w0.09: U27.M16@97.6,72 97.6,72.012 98,72.413 v2(98,72.425) ; U29.K2@115.5,67.225 v4(115.9,67.625) ; U28.K2@133.132,74.357 v4(133.525,74.75)
  Bottom Layer w0.09: v2(98,72.425) 98.345,72.77 98.345,75.92 99.386,76.961 109.669,76.961 115.684,70.946 ; 115.703,70.946 115.703,69.383 116.097,68.989 116.097,68.187 115.9,67.99 v4(115.9,67.625) 115.975,67.625 116.53,68.18 116.722,68.18 116.797,68.255 117.264,68.255 117.495,68.486 117.495,69.076 126.742,78.323 130.263,78.323 130.335,78.395 131.91,78.395 133.244,77.061 133.244,76.471 133.546,76.169 133.546,74.771 v4(133.525,74.75) 134.965,74.75 135.75,75.535 135.75,76.4 135.375,76.775 135.375,77 R259.1@135.2,77.175
DDR_CLK_N: R270.2 U27.M19 U28.K8 U29.K8 | length 53.6
  Top Layer w0.09: U27.M19@100,72 100.295,71.705 101.964,71.705 102.369,71.3 102.625,71.3 v2(102.775,71.45) ; U29.K8@115.494,62.422 115.494,62.472 115.847,62.825 v4(115.9,62.825) ; U28.K8@133.125,69.525 U28.K8@133.125,69.55 133.125,69.575 133.478,69.928 v4@133.532,69.928
  Bottom Layer w0.09: v2(102.775,71.45) 102.859,71.45 102.981,71.328 103.454,71.328 103.91,71.785 104.607,71.785 104.917,71.475 104.917,70.099 106.345,68.671 106.345,66.508 106.489,66.365 106.9,66.365 107.435,66.9 108.025,66.9 108.287,66.638 108.287,66.089 108.563,65.813 110.909,65.813 111.122,65.6 112.403,65.6 114.417,63.586 115.411,63.586 115.616,63.38 115.616,63.03 115.794,62.852 115.794,62.764 115.614,62.584 115.614,62.427 115.729,62.312 115.96,62.312 117.201,63.553 118.301,63.553 118.569,63.821 120.105,63.821 120.517,64.233 121.613,64.233 124.08,66.7 124.08,70.33 126.227,72.477 126.3,72.55 130.155,72.55 131.986,70.719 132.938,70.719 133.232,70.425 133.232,70.22 133.502,69.95 v4(133.525,69.95) 133.25,69.675 133.25,69.534 133.388,69.396 135.392,69.396 135.721,69.725 R270.2@135.75,69.725
DDR_CLK_P: R270.1 U27.N19 U28.K7 U29.K7 | length 53.5
  Top Layer w0.09: U27.N19@100,71.2 100.325,71.525 101.89,71.525 102.315,71.1 102.625,71.1 v2(102.775,70.95) ; v4(115.1,62.825) 115.147,62.825 115.494,63.172 U29.K7@115.494,63.222 ; v4@132.778,69.928 133.125,70.275 U28.K7@133.125,70.325
  Bottom Layer w0.09: v2(102.775,70.95) 102.855,70.95 102.983,71.078 103.557,71.078 104.014,71.535 104.504,71.535 104.667,71.371 104.667,69.996 106.095,68.568 106.095,66.405 106.385,66.115 107.004,66.115 107.539,66.65 107.921,66.65 108.037,66.535 108.037,65.985 108.459,65.563 110.806,65.563 111.018,65.35 112.299,65.35 114.313,63.336 115.307,63.336 115.366,63.277 115.366,63.03 v4@115.194,62.857 ; v4(115.1,62.825) 115.127,62.825 115.364,62.589 115.364,62.324 115.625,62.062 116.063,62.062 117.304,63.303 118.404,63.303 118.672,63.571 120.209,63.571 120.621,63.983 121.717,63.983 124.33,66.596 124.33,70.227 126.404,72.3 130.051,72.3 131.882,70.469 132.834,70.469 132.982,70.321 132.982,70.206 v4(132.725,69.95) 133,69.675 133,69.43 133.285,69.146 135.382,69.146 135.703,68.825 R270.1@135.75,68.825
